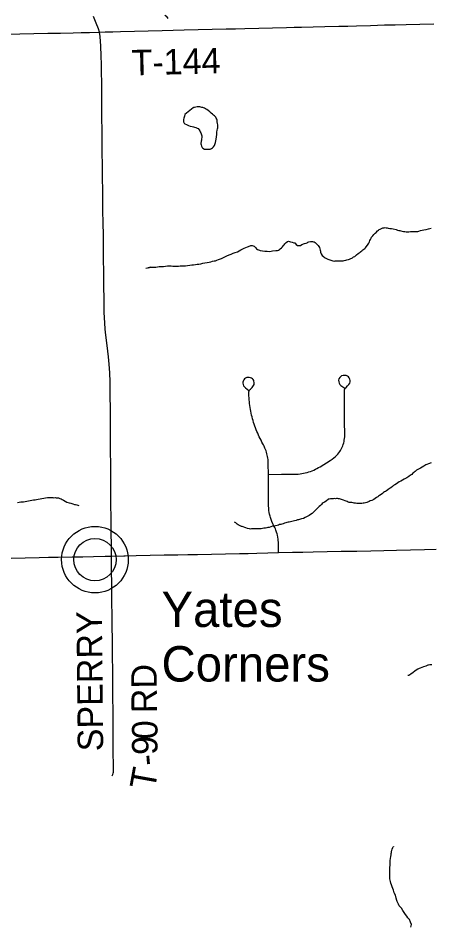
# Model space of a CAD drawing. Extents: x 103424 to 286016, y 38711 to 110967.
# Drawn here: x 121217 to 126106, y 53149 to 63924 of the extents above; entities that cross this region are included whole.
import ezdxf

# ---------------------------------------------------------------- set-up
doc = ezdxf.new("R2010")
doc.units = 0
for name, color, linetype in [('GM_X_County_Road', 7, 'Continuous'), ('GM_X_Minor_Lake', 7, 'Continuous'), ('GM_X_Minor_River', 7, 'Continuous'), ('GM_X_State_Route', 7, 'Continuous'), ('GM_X_Township_Road', 7, 'Continuous'), ('GM_X_Township_Road_Text', 7, 'Continuous'), ('GM_X_Unincorporated', 7, 'Continuous'), ('GM_X_Unincorporated_Location', 7, 'Continuous'), ('GM_X_Unincorporated_Text', 7, 'Continuous')]:
    doc.layers.add(name, color=color, linetype=linetype)

msp = doc.modelspace()

# ---------------------------------------------------------------- linework, layer by layer
at = {"layer": 'GM_X_County_Road'}
for points in [[(122180, 63757), (122167, 63799), (122141, 63865), (122110, 63943)], [(122323, 57545), (122321, 57666), (122319, 57831), (122318, 57996), (122316, 58161), (122315, 58313), (122314, 58464), (122313, 58629), (122312, 58794), (122311, 58959), (122310, 59124), (122309, 59289), (122308, 59451), (122307, 59613), (122303, 59719), (122297, 59821), (122287, 59909), (122272, 60044), (122256, 60164), (122248, 60238), (122242, 60312), (122237, 60433), (122234, 60590), (122233, 60745), (122231, 60910), (122229, 61075), (122227, 61240), (122226, 61364), (122224, 61487), (122222, 61652), (122220, 61762), (122219, 61872), (122217, 62037), (122215, 62202), (122214, 62310), (122213, 62419), (122212, 62584), (122210, 62749), (122209, 62894), (122208, 63040), (122207, 63160), (122206, 63279), (122203, 63377), (122200, 63475), (122196, 63594), (122192, 63649), (122188, 63706), (122180, 63757)]]:
    msp.add_lwpolyline(points, dxfattribs=at)
at = {"layer": 'GM_X_Minor_Lake'}
for points in [[(123290, 62860), (123193, 62783), (123186, 62763), (123178, 62740), (123174, 62722), (123175, 62706), (123177, 62694), (123183, 62680), (123191, 62670), (123212, 62662), (123234, 62653), (123256, 62645), (123277, 62641), (123293, 62635), (123305, 62633), (123321, 62626), (123337, 62620), (123348, 62614), (123362, 62600), (123368, 62590), (123374, 62578), (123381, 62564), (123385, 62552), (123389, 62540), (123391, 62528), (123392, 62512), (123390, 62491), (123388, 62479), (123386, 62467), (123385, 62455), (123383, 62445), (123383, 62435), (123385, 62423), (123389, 62407), (123396, 62391), (123404, 62381), (123424, 62371), (123451, 62369), (123473, 62370), (123491, 62372), (123507, 62378), (123519, 62386), (123531, 62399), (123543, 62415), (123554, 62448), (123560, 62468), (123564, 62488), (123567, 62517), (123571, 62543), (123572, 62571), (123576, 62595), (123580, 62612), (123582, 62622), (123583, 62634), (123583, 62646), (123583, 62660), (123579, 62676), (123576, 62694), (123574, 62713), (123570, 62727), (123563, 62739), (123559, 62749), (123543, 62765), (123533, 62773), (123518, 62784), (123504, 62796), (123486, 62812), (123467, 62828), (123451, 62840), (123436, 62850), (123426, 62856), (123414, 62860), (123404, 62863), (123392, 62865), (123380, 62867), (123368, 62871), (123347, 62871), (123337, 62872), (123323, 62870), (123305, 62866), (123295, 62864), (123290, 62860)], [(123290, 62860), (123193, 62783), (123186, 62763), (123178, 62740), (123174, 62722), (123175, 62706), (123177, 62694), (123183, 62680), (123191, 62670), (123212, 62662), (123234, 62653), (123256, 62645), (123277, 62641), (123293, 62635), (123305, 62633), (123321, 62626), (123337, 62620), (123348, 62614), (123362, 62600), (123368, 62590), (123374, 62578), (123381, 62564), (123385, 62552), (123389, 62540), (123391, 62528), (123392, 62512), (123390, 62491), (123388, 62479), (123386, 62467), (123385, 62455), (123383, 62445), (123383, 62435), (123385, 62423), (123389, 62407), (123396, 62391), (123404, 62381), (123424, 62371), (123451, 62369), (123473, 62370), (123491, 62372), (123507, 62378)], [(123507, 62378), (123519, 62386), (123531, 62399), (123543, 62415), (123554, 62448), (123560, 62468), (123564, 62488), (123567, 62517), (123571, 62543), (123572, 62571), (123576, 62595), (123580, 62612), (123582, 62622), (123583, 62634), (123583, 62646), (123583, 62660), (123579, 62676), (123576, 62694), (123574, 62713), (123570, 62727), (123563, 62739), (123559, 62749), (123543, 62765), (123533, 62773), (123518, 62784), (123504, 62796), (123486, 62812), (123467, 62828), (123451, 62840), (123436, 62850), (123426, 62856), (123414, 62860), (123404, 62863), (123392, 62865), (123380, 62867), (123368, 62871), (123347, 62871), (123337, 62872), (123323, 62870), (123305, 62866), (123295, 62864), (123290, 62860)]]:
    msp.add_lwpolyline(points, dxfattribs=at)
at = {"layer": 'GM_X_Minor_River'}
for points in [[(122956, 63959), (122974, 63947), (122976, 63945), (122991, 63919)], [(124724, 61271), (124734, 61265), (124745, 61255), (124757, 61243), (124771, 61227), (124780, 61215), (124786, 61205), (124794, 61173), (124797, 61161), (124799, 61149), (124803, 61139), (124807, 61129), (124818, 61111), (124834, 61099), (124844, 61091), (124856, 61083), (124871, 61075), (124885, 61067), (124897, 61064), (124909, 61060), (124921, 61056), (124932, 61050), (124944, 61048), (124960, 61044), (124974, 61045), (124990, 61045), (125010, 61045), (125027, 61045), (125039, 61046), (125049, 61046), (125067, 61046), (125081, 61050), (125097, 61055), (125111, 61059), (125129, 61061), (125143, 61066), (125157, 61074), (125169, 61078), (125179, 61084), (125191, 61093), (125205, 61099), (125215, 61107), (125227, 61119), (125245, 61132), (125257, 61140), (125267, 61150), (125277, 61159), (125289, 61167), (125301, 61177), (125313, 61186), (125323, 61194), (125333, 61202), (125362, 61243), (125372, 61255), (125378, 61271), (125384, 61288), (125390, 61298), (125399, 61316), (125405, 61328), (125419, 61343), (125429, 61357), (125447, 61376), (125457, 61384), (125475, 61402), (125485, 61411), (125495, 61417), (125507, 61423), (125521, 61429), (125537, 61436), (125553, 61438), (125563, 61440), (125577, 61438), (125587, 61436), (125601, 61435), (125622, 61431), (125640, 61429), (125658, 61426), (125696, 61418), (125711, 61412), (125725, 61408), (125739, 61405), (125751, 61401), (125765, 61399), (125782, 61395), (125796, 61393), (125812, 61392), (125830, 61392), (125846, 61392), (125866, 61393), (125882, 61393), (125899, 61393), (125915, 61393), (125929, 61394), (125941, 61394), (125953, 61396), (125963, 61398), (125985, 61405), (126003, 61411), (126025, 61415), (126052, 61420), (126080, 61426)], [(126080, 61426), (126108, 61435)], [(122730, 60961), (122788, 60970), (122756, 60964), (122788, 60970), (122848, 60973), (122887, 60978), (122915, 60979), (122939, 60981), (122963, 60983), (122985, 60986), (123010, 60986), (123030, 60986), (123050, 60985), (123070, 60985), (123090, 60983), (123115, 60984), (123135, 60986), (123155, 60986), (123177, 60987), (123199, 60989), (123223, 60992), (123252, 60994), (123276, 60999), (123296, 61001), (123318, 61003), (123338, 61006), (123358, 61008), (123381, 61010), (123403, 61017), (123481, 61032), (123501, 61035), (123521, 61041), (123539, 61045), (123555, 61048), (123572, 61054), (123592, 61062), (123624, 61073), (123642, 61081), (123664, 61094), (123688, 61104), (123716, 61117), (123740, 61127), (123764, 61136), (123788, 61146), (123814, 61155), (123834, 61167), (123854, 61176), (123870, 61184), (123896, 61195), (123914, 61205), (123932, 61211), (123944, 61218), (123954, 61220), (123964, 61224), (123974, 61228), (123988, 61228), (124011, 61219), (124027, 61203), (124041, 61189), (124054, 61181), (124064, 61177), (124076, 61173), (124086, 61169), (124113, 61164), (124141, 61162), (124167, 61161), (124193, 61159), (124215, 61161), (124232, 61166), (124268, 61170), (124288, 61171), (124300, 61173), (124314, 61179), (124322, 61189), (124336, 61200), (124348, 61212), (124358, 61224), (124370, 61237), (124377, 61249), (124393, 61265), (124407, 61274), (124421, 61278), (124442, 61272), (124462, 61267), (124484, 61261), (124496, 61259), (124511, 61241), (124527, 61229), (124547, 61228), (124561, 61230), (124579, 61240), (124609, 61251), (124630, 61257), (124640, 61261), (124650, 61266), (124662, 61270), (124680, 61276), (124692, 61276), (124704, 61275), (124714, 61273), (124724, 61271)], [(126108, 58653), (126080, 58640), (126058, 58632), (126046, 58628), (126024, 58611), (126004, 58601), (125982, 58588), (125958, 58576), (125946, 58569), (125936, 58563), (125920, 58549), (125910, 58541), (125900, 58532), (125890, 58524), (125880, 58514), (125864, 58504), (125846, 58489), (125822, 58473), (125792, 58458), (125770, 58445), (125750, 58435), (125732, 58427), (125716, 58416), (125699, 58402), (125681, 58391), (125665, 58381), (125651, 58369), (125631, 58356), (125615, 58346), (125595, 58331), (125581, 58321), (125569, 58313), (125557, 58307), (125547, 58298), (125535, 58286), (125517, 58276)], [(121210, 58181), (121228, 58183), (121248, 58187), (121279, 58190), (121301, 58192), (121321, 58197), (121341, 58201), (121359, 58205), (121379, 58208), (121399, 58212), (121418, 58214), (121436, 58217), (121454, 58219), (121520, 58232), (121542, 58237), (121564, 58241), (121581, 58241), (121591, 58242), (121601, 58242), (121615, 58242), (121627, 58240), (121639, 58238), (121655, 58239), (121667, 58237), (121684, 58237), (121694, 58235), (121712, 58229), (121726, 58226), (121738, 58218), (121755, 58208), (121773, 58196), (121795, 58186), (121820, 58177), (121840, 58171), (121866, 58165), (121885, 58159), (121897, 58158), (121913, 58152), (121923, 58148), (121937, 58144), (121937, 58144)], [(125517, 58276), (125499, 58263), (125487, 58257), (125477, 58249), (125463, 58240), (125447, 58230), (125429, 58218), (125407, 58205), (125389, 58201), (125375, 58192), (125349, 58182), (125315, 58173), (125303, 58171), (125287, 58169), (125275, 58169), (125261, 58168), (125246, 58170), (125228, 58170), (125212, 58172), (125198, 58173), (125184, 58175), (125170, 58179), (125149, 58181), (125137, 58182), (125125, 58186), (125113, 58192), (125103, 58196), (125090, 58200), (125070, 58208), (125058, 58211), (125048, 58215), (125023, 58223), (125011, 58225), (124999, 58227), (124989, 58227), (124977, 58226), (124967, 58228), (124953, 58226), (124941, 58226), (124929, 58226), (124917, 58223), (124902, 58221), (124892, 58219), (124867, 58196), (124845, 58184), (124829, 58175), (124819, 58167), (124809, 58159), (124797, 58147), (124783, 58132), (124767, 58116), (124757, 58106), (124725, 58075), (124713, 58064), (124699, 58052), (124681, 58040), (124664, 58027), (124640, 58013), (124616, 58002), (124598, 57992), (124575, 57987), (124563, 57983), (124551, 57979), (124537, 57977), (124525, 57974), (124509, 57968), (124491, 57964), (124475, 57960), (124459, 57955), (124445, 57951), (124429, 57949), (124415, 57946), (124401, 57942), (124387, 57940), (124372, 57934), (124356, 57929), (124342, 57925), (124328, 57921), (124314, 57918), (124300, 57914), (124284, 57910), (124266, 57906), (124248, 57901), (124230, 57899), (124212, 57893), (124192, 57886), (124176, 57884), (124162, 57880), (124147, 57877), (124137, 57877), (124127, 57875), (124113, 57873), (124097, 57870), (124083, 57868), (124057, 57868), (124041, 57868), (124027, 57867), (124012, 57867), (123998, 57867), (123982, 57867), (123968, 57866)], [(123968, 57866), (123958, 57868), (123932, 57874), (123913, 57882), (123903, 57885), (123883, 57891), (123871, 57895), (123861, 57897), (123848, 57903), (123832, 57913), (123822, 57916), (123812, 57922), (123795, 57938), (123781, 57946), (123781, 57948)], [(126116, 56255), (126096, 56255), (126080, 56252), (126070, 56250), (126046, 56242), (126021, 56233), (125999, 56225), (125979, 56218), (125967, 56212), (125951, 56204), (125931, 56193), (125917, 56181), (125895, 56163), (125870, 56144), (125844, 56131), (125833, 56129)], [(125642, 54055), (125648, 54072), (125654, 54088), (125658, 54098), (125662, 54100), (125662, 54098)], [(125871, 53146), (125875, 53178), (125864, 53206), (125852, 53235), (125835, 53256), (125821, 53276), (125806, 53296), (125792, 53318), (125775, 53342), (125759, 53370), (125742, 53386), (125732, 53398), (125722, 53416), (125715, 53434), (125707, 53448), (125703, 53462), (125696, 53491), (125686, 53523), (125673, 53553), (125662, 53583), (125648, 53623), (125639, 53649), (125633, 53667), (125628, 53687), (125624, 53704), (125622, 53720), (125621, 53736), (125621, 53756), (125621, 53776), (125620, 53798), (125620, 53823), (125623, 53910), (125626, 53936), (125630, 53960), (125633, 53984), (125635, 54003), (125637, 54019), (125639, 54031), (125640, 54045), (125642, 54055)]]:
    msp.add_lwpolyline(points, dxfattribs=at)
at = {"layer": 'GM_X_State_Route'}
for points in [[(119812, 57494), (119977, 57497), (120142, 57500), (120307, 57503), (120472, 57506), (120637, 57510), (120730, 57511), (120823, 57513), (120951, 57516), (121079, 57519), (121136, 57521), (121301, 57524), (121466, 57528), (121578, 57531), (121690, 57533), (121855, 57536), (121983, 57538), (122111, 57541), (122249, 57544), (122323, 57545), (122469, 57549), (122485, 57549)], [(122485, 57549), (122615, 57553), (122780, 57556), (122945, 57559), (123110, 57562), (123226, 57564), (123343, 57566), (123508, 57569), (123673, 57572), (123838, 57576), (123940, 57578), (124043, 57580), (124173, 57583), (124303, 57586), (124468, 57590), (124590, 57593), (124713, 57596), (124878, 57599), (125043, 57602), (125137, 57604), (125231, 57605), (125396, 57609), (125548, 57613), (125699, 57616), (125864, 57620), (126029, 57623), (126168, 57626)]]:
    msp.add_lwpolyline(points, dxfattribs=at)
at = {"layer": 'GM_X_Township_Road'}
for points in [[(122180, 63757), (122167, 63799), (122141, 63865), (122110, 63943)], [(122180, 63757), (122248, 63760), (122338, 63763), (122429, 63765), (122594, 63770), (122759, 63774), (122924, 63778), (123055, 63782), (123185, 63785), (123351, 63789), (123516, 63793), (123681, 63797), (123791, 63799), (123902, 63802), (124067, 63806), (124232, 63810), (124397, 63814), (124486, 63816), (124575, 63818), (124713, 63821), (124852, 63825), (125017, 63829), (125121, 63831), (125226, 63834), (125391, 63838), (125556, 63843), (125684, 63846), (125812, 63850), (125977, 63854), (126142, 63858)], [(121072, 63735), (121237, 63738), (121402, 63742), (121567, 63745), (121717, 63748), (121867, 63751), (121965, 63753), (122063, 63755), (122180, 63757)], [(122323, 57545), (122321, 57666), (122319, 57831), (122318, 57996), (122316, 58161), (122315, 58313), (122314, 58464), (122313, 58629), (122312, 58794), (122311, 58959), (122310, 59124), (122309, 59289), (122308, 59451), (122307, 59613), (122303, 59719), (122297, 59821), (122287, 59909), (122272, 60044), (122256, 60164), (122248, 60238), (122242, 60312), (122237, 60433), (122234, 60590), (122233, 60745), (122231, 60910), (122229, 61075), (122227, 61240), (122226, 61364), (122224, 61487), (122222, 61652), (122220, 61762), (122219, 61872), (122217, 62037), (122215, 62202), (122214, 62310), (122213, 62419), (122212, 62584), (122210, 62749), (122209, 62894), (122208, 63040), (122207, 63160), (122206, 63279), (122203, 63377), (122200, 63475), (122196, 63594), (122192, 63649), (122188, 63706), (122180, 63757)], [(124303, 57586), (124302, 57687), (124301, 57712), (124299, 57729), (124297, 57746), (124293, 57771), (124288, 57795), (124284, 57811), (124279, 57828), (124271, 57851), (124264, 57867), (124258, 57883), (124250, 57898), (124236, 57926), (124224, 57954), (124214, 57981), (124207, 58002), (124201, 58020), (124195, 58043), (124191, 58062), (124188, 58086), (124185, 58110), (124184, 58146), (124183, 58311), (124182, 58413), (124182, 58514), (124180, 58638), (124179, 58655), (124178, 58673), (124177, 58690), (124174, 58708), (124171, 58725), (124168, 58742), (124164, 58759), (124159, 58776), (124154, 58793), (124147, 58810), (124141, 58826), (124130, 58850), (124122, 58866), (124116, 58878), (124105, 58898), (124094, 58919), (124084, 58939), (124074, 58960), (124064, 58980), (124055, 59001), (124046, 59022), (124038, 59044), (124029, 59065), (124022, 59086), (124014, 59108), (124007, 59130), (124001, 59152), (123995, 59174), (123989, 59196), (123983, 59218), (123978, 59240), (123974, 59262), (123969, 59285), (123965, 59307), (123962, 59330), (123959, 59353), (123956, 59375), (123954, 59398), (123952, 59421), (123950, 59444), (123949, 59466), (123949, 59494), (123952, 59506), (123958, 59515), (123968, 59525), (123990, 59546), (123999, 59555), (124007, 59569), (124012, 59582), (124014, 59597), (124009, 59626), (124003, 59638), (123995, 59647), (123983, 59655), (123970, 59661), (123955, 59664), (123939, 59665), (123925, 59662), (123912, 59657), (123899, 59648), (123890, 59636), (123883, 59620), (123880, 59606), (123880, 59594), (123883, 59579), (123888, 59566), (123898, 59551), (123910, 59539), (123951, 59510)], [(124182, 58514), (124338, 58515), (124494, 58516), (124515, 58517), (124536, 58518), (124557, 58521), (124578, 58524), (124598, 58528), (124619, 58532), (124639, 58538), (124660, 58544), (124680, 58550), (124699, 58558), (124719, 58566), (124738, 58575), (124757, 58584), (124775, 58594), (124794, 58605), (124913, 58680), (124936, 58696), (124955, 58710), (124975, 58726), (124992, 58742), (125005, 58755), (125016, 58769), (125027, 58784), (125036, 58799), (125048, 58820), (125056, 58837), (125063, 58853), (125069, 58870), (125074, 58888), (125079, 58905), (125081, 58920), (125084, 58940), (125086, 58959), (125087, 58982), (125085, 59147), (125084, 59312), (125083, 59407), (125082, 59502), (125083, 59518), (125086, 59528), (125093, 59538), (125101, 59546), (125119, 59563), (125136, 59581), (125145, 59597), (125149, 59612), (125149, 59629), (125145, 59644), (125139, 59658), (125129, 59671), (125117, 59680), (125103, 59685), (125084, 59688), (125066, 59687), (125049, 59681), (125038, 59673), (125026, 59662), (125018, 59648), (125014, 59630), (125015, 59612), (125019, 59596), (125029, 59580), (125040, 59568), (125087, 59537)], [(122329, 54939), (122338, 54956), (122343, 54970), (122347, 54984), (122347, 55015), (122346, 55078), (122344, 55204), (122343, 55369), (122342, 55534), (122341, 55621), (122341, 55707), (122340, 55872), (122339, 55967), (122339, 56062), (122337, 56227), (122336, 56314), (122335, 56401), (122333, 56566), (122331, 56702), (122329, 56838), (122327, 57003), (122326, 57121), (122325, 57238), (122324, 57352), (122323, 57466), (122323, 57545)]]:
    msp.add_lwpolyline(points, dxfattribs=at)
at = {"layer": 'GM_X_Unincorporated'}
for radius in [395, 251]:
    msp.add_circle((122127, 57503), radius, dxfattribs=at)
at = {"layer": 'GM_X_Unincorporated_Location'}
msp.add_line((122127, 57503), (122127, 57503), dxfattribs=at)

# ---------------------------------------------------------------- texts
at = {"layer": 'GM_X_Township_Road_Text'}
for s, height, rotation, p in [('T-144', 301.9, 1.4052, (122563, 63245)), ('SPERRY', 301.9, 90.5452, (122225, 55232)), ('RD', 301.9, 90.4948, (122862, 55684)), ('0', 302, 90.0364, (122868, 55373)), ('9', 302, 90.2706, (122868, 55188)), ('-', 302, 94.8912, (122879, 55071)), ('T', 302, 79.7323, (122834, 54762))]:
    msp.add_text(s, height=height, rotation=rotation, dxfattribs=at).set_placement(p)
at = {"layer": 'GM_X_Unincorporated_Text'}
for s, p in [('Yates', (122915, 56705)), ('Corners', (122915, 56058))]:
    msp.add_text(s, height=419.6, rotation=0, dxfattribs=at).set_placement(p)

doc.saveas('drawing.dxf')
